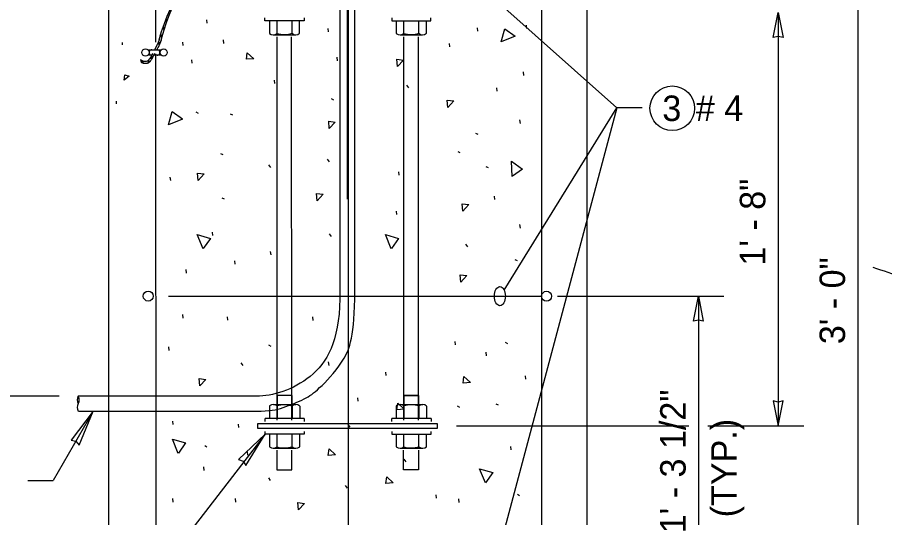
# Model space of a CAD drawing. Extents: x 99862 to 103680, y 99470 to 105076.
# Drawn here: x 101207 to 101751, y 103328 to 103642 of the extents above; entities that cross this region are included whole.
import ezdxf

# ---------------------------------------------------------------- set-up
doc = ezdxf.new("R2010")
doc.units = 0
for name, color, linetype in [('Level 1', 7, 'Continuous'), ('Level 10', 7, 'Continuous'), ('Level 11', 7, 'Continuous'), ('Level 12', 7, 'Continuous'), ('Level 15', 7, 'Continuous'), ('Level 19', 7, 'Continuous'), ('Level 20', 7, 'Continuous'), ('Level 24', 7, 'Continuous'), ('Level 25', 7, 'Continuous'), ('Level 3', 7, 'Continuous'), ('Level 37', 7, 'Continuous'), ('Level 4', 7, 'Continuous'), ('Level 8', 7, 'Continuous')]:
    doc.layers.add(name, color=color, linetype=linetype)

msp = doc.modelspace()

# ---------------------------------------------------------------- linework, layer by layer
at = {"layer": 'Level 1'}
msp.add_line((101564.13, 103688.38), (101564.17, 103232.26), dxfattribs=at)
msp.add_lwpolyline([(101264.13, 103688.38), (101264.17, 103232.26), (101564.17, 103232.26)], dxfattribs=at)
at = {"layer": 'Level 10'}
for centre in [(101289.13, 103466.63), (101538.93, 103466.58)]:
    msp.add_circle(centre, 3.12, dxfattribs=at)
at = {"layer": 'Level 11'}
for p, q in [((101326.18, 103637.91), (101325.95, 103640.09)), ((101402.15, 103632.4), (101401.92, 103634.57)), ((101495.85, 103632.81), (101495.62, 103634.98)), ((101526.51, 103634.59), (101526.28, 103636.76)), ((101311.03, 103623.8), (101310.8, 103625.97)), ((101336.49, 103625.24), (101336.26, 103627.42)), ((101478.27, 103623.08), (101478.03, 103625.25)), ((101316.77, 103612.82), (101316.54, 103615)), ((101407.92, 103614.34), (101407.69, 103616.51)), ((101524.74, 103605.13), (101524.52, 103607.31)), ((101368.6, 103599.99), (101368.37, 103602.17)), ((101451.16, 103598.95), (101452.35, 103597.33)), ((101507.95, 103595.25), (101507.72, 103597.43)), ((101403.77, 103590.57), (101405.21, 103589.86)), ((101318.96, 103582.19), (101320.4, 103581.48)), ((101340.48, 103581.06), (101341.92, 103580.36)), ((101522.48, 103575.03), (101522.25, 103577.2)), ((101494.35, 103568.91), (101495.78, 103568.2)), ((101334.47, 103556.17), (101335.9, 103555.46)), ((101401.35, 103552.6), (101402.54, 103550.99)), ((101483.19, 103557.38), (101484.63, 103556.67)), ((101364.55, 103548.95), (101365.74, 103547.33)), ((101500.86, 103548.01), (101502.29, 103547.3)), ((101446.58, 103542.46), (101446.35, 103544.63)), ((101303.19, 103539.13), (101302.96, 103541.31)), ((101335.31, 103528.37), (101336.75, 103527.66)), ((101506.46, 103527.23), (101506.23, 103529.41)), ((101445.09, 103517.84), (101444.87, 103520.02)), ((101522.49, 103509.37), (101522.26, 103511.55)), ((101329.6, 103504.66), (101329.37, 103506.83)), ((101402.57, 103505.76), (101403.76, 103504.14)), ((101488.19, 103499.21), (101489.38, 103497.59)), ((101366.12, 103492.46), (101365.89, 103494.63)), ((101343.71, 103486.71), (101343.48, 103488.89)), ((101518.97, 103489.7), (101520.41, 103488.99)), ((101313.12, 103481.12), (101312.89, 103483.3)), ((101311.03, 103452.9), (101310.8, 103455.08)), ((101339.06, 103451.46), (101338.83, 103453.64)), ((101392.54, 103451.45), (101392.31, 103453.63)), ((101481.85, 103436.08), (101481.63, 103438.25)), ((101302.19, 103432.55), (101301.95, 103434.73)), ((101364.51, 103436.02), (101365.95, 103435.31)), ((101512.99, 103437.65), (101514.43, 103436.94)), ((101501.22, 103429.28), (101501, 103431.45)), ((101347.25, 103424.8), (101348.44, 103423.18)), ((101402.49, 103423.14), (101402.27, 103425.32)), ((101438.26, 103416.81), (101438.04, 103418.99)), ((101525.87, 103414.49), (101525.64, 103416.67)), ((101420.84, 103400.66), (101420.61, 103402.83)), ((101482.94, 103397.72), (101484.38, 103397.01)), ((101507.19, 103399.09), (101508.63, 103398.39)), ((101304.8, 103386.04), (101304.57, 103388.21)), ((101345.94, 103384.2), (101345.71, 103386.37)), ((101414.33, 103386.09), (101415.52, 103384.47)), ((101324.53, 103372.89), (101325.96, 103372.18)), ((101351.66, 103366.81), (101351.43, 103368.99)), ((101516.8, 103370.16), (101516.57, 103372.34)), ((101449.42, 103364.25), (101450.61, 103362.64)), ((101324.13, 103357.29), (101323.89, 103359.47)), ((101364.49, 103352.65), (101365.68, 103351.03)), ((101412.69, 103347.84), (101413.88, 103346.22)), ((101469.84, 103339.78), (101469.61, 103341.95)), ((101520.6, 103342.29), (101522.03, 103341.58)), ((101304.8, 103337.39), (101304.57, 103339.56)), ((101344.02, 103337.39), (101343.79, 103339.56)), ((101484.21, 103337.24), (101483.98, 103339.41))]:
    msp.add_line(p, q, dxfattribs=at)
for points in [[(101519.28, 103629.76), (101510.38, 103626.15), (101512.72, 103634.35)], [(101512.73, 103634.37), (101519.28, 103629.76)], [(101355.29, 103615.61), (101350.68, 103615.26), (101351.18, 103619.39), (101355.29, 103615.61)], [(101445.45, 103610.69), (101445.09, 103615.29), (101449.23, 103614.79), (101445.45, 103610.69)], [(101476.96, 103585.04), (101476.61, 103589.65), (101480.75, 103589.15), (101476.96, 103585.04)], [(101310.64, 103577.76), (101301.74, 103574.15), (101304.09, 103582.39), (101310.51, 103577.87)], [(101402.66, 103571.73), (101402.31, 103576.33), (101406.44, 103575.83), (101402.66, 103571.73)], [(101517.33, 103541.74), (101516.98, 103551.34), (101523.92, 103546.32), (101517.47, 103541.83)], [(101320.41, 103539.24), (101320.06, 103543.84), (101324.19, 103543.34), (101320.41, 103539.24)], [(101395.09, 103526.44), (101394.74, 103531.04), (101398.87, 103530.54), (101395.09, 103526.44)], [(101486.4, 103520), (101486.05, 103524.6), (101490.18, 103524.11), (101486.4, 103520)], [(101323.47, 103496.34), (101319.86, 103505.24), (101328.1, 103502.89), (101323.58, 103496.46)], [(101441.52, 103496.34), (101437.91, 103505.24), (101446.15, 103502.89), (101441.63, 103496.46)], [(101485.17, 103475.45), (101484.82, 103480.06), (101488.95, 103479.56), (101485.17, 103475.45)], [(101491.22, 103412.47), (101486.61, 103412.12), (101487.11, 103416.25), (101491.22, 103412.47)], [(101321.5, 103410.26), (101321.15, 103414.86), (101325.28, 103414.36), (101321.5, 103410.26)], [(101449.7, 103395.71), (101445.1, 103395.36), (101445.6, 103399.49), (101449.7, 103395.71)], [(101307.95, 103367.94), (101304.34, 103376.84), (101312.58, 103374.49), (101308.06, 103368.07)], [(101406.62, 103366.96), (101402.01, 103366.61), (101402.51, 103370.74), (101406.62, 103366.96)], [(101500.53, 103349.44), (101496.92, 103358.34), (101505.16, 103355.99), (101500.64, 103349.57)], [(101442.82, 103349.4), (101438.22, 103349.05), (101438.72, 103353.19), (101442.82, 103349.4)], [(101383.29, 103332.45), (101382.94, 103337.06), (101387.08, 103336.56), (101383.29, 103332.45)]]:
    msp.add_lwpolyline(points, dxfattribs=at)
at = {"layer": 'Level 12'}
for p, q in [((101365.17, 103639.37), (101365.17, 103631.45)), ((101369.9, 103631.45), (101369.9, 103639.37)), ((101379.35, 103631.54), (101379.35, 103639.41)), ((101384.08, 103631.54), (101384.08, 103639.46)), ((101444.66, 103639.37), (101444.66, 103631.45)), ((101449.39, 103631.45), (101449.39, 103639.37)), ((101458.84, 103631.54), (101458.84, 103639.46)), ((101463.57, 103631.54), (101463.57, 103639.46)), ((101367.69, 103630.65), (101381.72, 103630.65)), ((101447.18, 103630.65), (101461.21, 103630.65)), ((101365.21, 103397.77), (101365.21, 103389.85)), ((101367.73, 103398.57), (101381.75, 103398.57)), ((101369.93, 103397.77), (101369.93, 103389.85)), ((101379.39, 103397.69), (101379.39, 103389.77)), ((101384.12, 103397.69), (101384.12, 103389.77)), ((101444.7, 103397.77), (101444.7, 103389.85)), ((101447.22, 103398.57), (101461.25, 103398.57)), ((101449.43, 103397.77), (101449.43, 103389.85)), ((101458.88, 103397.69), (101458.88, 103389.77)), ((101463.61, 103397.69), (101463.61, 103389.77)), ((101386.97, 103389.81), (101362.36, 103389.81)), ((101362.36, 103388.05), (101362.36, 103389.81)), ((101386.97, 103389.81), (101386.97, 103388.05)), ((101466.46, 103389.81), (101441.85, 103389.81)), ((101441.85, 103388.05), (101441.85, 103389.81)), ((101466.46, 103389.81), (101466.46, 103388.05)), ((101365.21, 103380), (101365.21, 103372.08)), ((101369.93, 103372.08), (101369.93, 103380)), ((101379.39, 103372.16), (101379.39, 103380.04)), ((101384.12, 103372.16), (101384.12, 103380.08)), ((101444.7, 103380), (101444.7, 103372.08)), ((101449.43, 103372.08), (101449.43, 103380)), ((101458.88, 103372.16), (101458.88, 103380.08)), ((101463.61, 103372.16), (101463.61, 103380.08)), ((101367.73, 103371.28), (101381.75, 103371.28)), ((101447.22, 103371.28), (101461.25, 103371.28))]:
    msp.add_line(p, q, dxfattribs=at)
for points in [[(101386.93, 103641.17), (101386.93, 103639.41), (101362.32, 103639.41), (101362.32, 103641.17)], [(101441.81, 103641.17), (101441.81, 103639.41), (101466.42, 103639.41), (101466.42, 103641.17)], [(101386.97, 103381.8), (101386.97, 103380.04), (101362.36, 103380.04), (101362.36, 103381.8)], [(101441.85, 103381.8), (101441.85, 103380.04), (101466.46, 103380.04), (101466.46, 103381.8)]]:
    msp.add_lwpolyline(points, dxfattribs=at)
for centre, radius, start, end in [((101367.53, 103634.55), 3.9, 232.6587, 307.3413), ((101374.48, 103646.27), 15.52, 252.8169, 288.2986), ((101381.72, 103634.26), 3.61, 229.0578, 310.9523), ((101447.02, 103634.55), 3.9, 232.6587, 307.3413), ((101453.97, 103646.27), 15.52, 252.8169, 288.2986), ((101461.21, 103634.26), 3.61, 229.0578, 310.9523), ((101367.57, 103394.68), 3.9, 52.6587, 127.3413), ((101374.52, 103382.95), 15.52, 71.7014, 107.1831), ((101381.75, 103394.96), 3.61, 49.0477, 130.9422), ((101447.06, 103394.68), 3.9, 52.6587, 127.3413), ((101454.01, 103382.95), 15.52, 71.7014, 107.1831), ((101461.25, 103394.96), 3.61, 49.0477, 130.9422), ((101367.57, 103375.17), 3.9, 232.6587, 307.3413), ((101374.52, 103386.9), 15.52, 252.8169, 288.2986), ((101381.75, 103374.89), 3.61, 229.0578, 310.9523), ((101447.06, 103375.17), 3.9, 232.6587, 307.3413), ((101454.01, 103386.9), 15.52, 252.8169, 288.2986), ((101461.25, 103374.89), 3.61, 229.0578, 310.9523)]:
    msp.add_arc(centre, radius, start, end, dxfattribs=at)
at = {"layer": 'Level 15'}
for p, q in [((101734.13, 103694.63), (101734.17, 103232.26)), ((101582.9, 103584.75), (101494.85, 103663.38)), ((101684.13, 103644.56), (101684.17, 103385.18)), ((101582.9, 103584.75), (101497.99, 103265.63)), ((101512.4, 103470.32), (101582.9, 103584.75)), ((101598.9, 103584.75), (101582.9, 103584.75)), ((101545.83, 103466.58), (101650.13, 103466.58)), ((101634.13, 103466.58), (101634.17, 103262.24)), ((101233.25, 103403.85), (101008.17, 103403.85)), ((101254.69, 103394.48), (101229.54, 103350.91)), ((101482.42, 103385.18), (101628.17, 103385.18)), ((101640.17, 103385.18), (101700.17, 103385.18)), ((101362.36, 103380.04), (101210.75, 103183.32)), ((101213.54, 103350.91), (101229.54, 103350.91))]:
    msp.add_line(p, q, dxfattribs=at)
for points in [[(101684.13, 103644.56), (101687.22, 103628.83), (101684.13, 103629.56), (101681.05, 103628.83)], [(101634.13, 103466.58), (101637.22, 103450.86), (101634.13, 103451.59), (101631.05, 103450.86)], [(101684.17, 103385.18), (101687.26, 103400.91), (101684.17, 103400.18), (101681.09, 103400.91)], [(101254.69, 103394.48), (101240.69, 103376.2), (101243.8, 103375.62), (101245.86, 103373.21)], [(101362.37, 103380.03), (101345.64, 103364.22), (101348.62, 103363.15), (101350.26, 103360.45)]]:
    msp.add_lwpolyline(points, close=True, dxfattribs=at)
for centre, start, end in [((101249.28, 103401.52), 150, 210), ((101241.22, 103401.52), 330, 30), ((101249.28, 103396.87), 150, 210.9241)]:
    msp.add_arc(centre, 4.66, start, end, dxfattribs=at)
msp.add_ellipse((101509.66, 103466.63), major_axis=(0, 6), ratio=0.57735, dxfattribs=at)
at = {"layer": 'Level 19'}
for p, q in [((101272.9, 103624.27), (101273.01, 103625.84)), ((101269.19, 103587.39), (101269.3, 103588.97))]:
    msp.add_line(p, q, dxfattribs=at)
msp.add_lwpolyline([(101274.03, 103602.14), (101274.36, 103605.45), (101277.23, 103604.58), (101274.03, 103602.14)], dxfattribs=at)
at = {"layer": 'Level 20'}
msp.add_circle((101617.79, 103584.51), 14, dxfattribs=at)
at = {"layer": 'Level 24'}
msp.add_lwpolyline([(101470.42, 103383.62), (101357.92, 103383.62), (101357.92, 103386.75), (101470.42, 103386.75)], close=True, dxfattribs=at)
at = {"layer": 'Level 25'}
for p, q in [((101293.77, 103754.2), (101293.77, 103625.98)), ((101535.8, 103754.2), (101535.84, 103262.15)), ((101414.02, 103527.42), (101414.02, 103752.42)), ((101414.42, 103650.5), (101414.46, 103262.15)), ((101293.77, 103618.71), (101293.81, 103262.15)), ((101301.84, 103466.63), (101535.8, 103466.63))]:
    msp.add_line(p, q, dxfattribs=at)
at = {"layer": 'Level 3'}
for p, q in [((101409.28, 103754.13), (101409.28, 103464.89)), ((101418.65, 103464.75), (101418.65, 103754.13)), ((101264.08, 103403.85), (101245.25, 103403.85)), ((101357.16, 103403.85), (101264.12, 103403.85)), ((101245.29, 103394.48), (101264.13, 103394.48)), ((101264.15, 103394.48), (101357.14, 103394.48))]:
    msp.add_line(p, q, dxfattribs=at)
for points in [[(101357.14, 103394.48), (101365.25, 103394.46), (101373.29, 103396.11), (101388.18, 103402.42), (101395, 103407.16), (101411.47, 103424.2), (101418.28, 103439.38), (101418.65, 103464.75)], [(101409.28, 103464.89), (101408.82, 103437.99), (101393.54, 103411.59), (101366.76, 103403.83), (101357.16, 103403.85)]]:
    msp.add_open_spline(points, degree=3, dxfattribs=at)
at = {"layer": 'Level 37'}
msp.add_ellipse((102885.43, 104054.93), major_axis=(1749.63, 26.45), ratio=0.419197, start_param=3.995063, end_param=4.008995, dxfattribs=at)
at = {"layer": 'Level 4'}
for p, q in [((101369.67, 103629.4), (101369.71, 103388.74)), ((101379.08, 103388.74), (101379.05, 103629.4)), ((101449.22, 103629.4), (101449.26, 103388.74)), ((101458.63, 103388.74), (101458.6, 103629.4)), ((101446.85, 103466.63), (101446.95, 103466.63)), ((101371.29, 103404.26), (101369.92, 103404.26)), ((101371.29, 103404.26), (101369.92, 103404.26)), ((101369.92, 103404.26), (101369.92, 103398.57)), ((101379.29, 103404.26), (101371.29, 103404.26)), ((101379.29, 103404.26), (101371.29, 103404.26)), ((101379.29, 103398.57), (101379.29, 103404.26)), ((101458.84, 103404.26), (101449.47, 103404.26)), ((101449.47, 103404.26), (101457.47, 103404.26)), ((101449.47, 103404.26), (101449.47, 103398.57)), ((101457.47, 103404.26), (101458.84, 103404.26)), ((101458.84, 103398.57), (101458.84, 103404.26))]:
    msp.add_line(p, q, dxfattribs=at)
for points in [[(101369.71, 103370.02), (101369.71, 103357.72), (101379.08, 103357.72), (101379.08, 103370.02)], [(101458.63, 103370.02), (101458.63, 103357.72), (101449.26, 103357.72), (101449.26, 103370.02)]]:
    msp.add_lwpolyline(points, dxfattribs=at)
at = {"layer": 'Level 8'}
for p, q in [((101301.14, 103639.93), (101300.24, 103639.93)), ((101298, 103634.28), (101298.9, 103634.28)), ((101299.22, 103635.12), (101298.32, 103635.12)), ((101299.89, 103639.1), (101300.8, 103639.1)), ((101296.28, 103629.46), (101297.16, 103629.46)), ((101297.45, 103630.3), (101296.57, 103630.3)), ((101295.06, 103624.89), (101295.94, 103624.89)), ((101296.23, 103625.73), (101295.35, 103625.73)), ((101288.86, 103621.24), (101297.32, 103621.24)), ((101291.27, 103617.8), (101288.86, 103617.81)), ((101297.32, 103617.8), (101291.27, 103617.8)), ((101284.27, 103614.86), (101284.7, 103613.29)), ((101285.93, 103614.05), (101285.07, 103614.37)), ((101285.07, 103614.37), (101285.13, 103613.28)), ((101285.13, 103613.28), (101285.99, 103612.95)), ((101285.99, 103612.95), (101285.93, 103614.05)), ((101289.06, 103614.36), (101288.99, 103614.32)), ((101288.99, 103614.32), (101289.13, 103613.41)), ((101289.92, 103613.93), (101289.06, 103614.36)), ((101289.13, 103613.41), (101289.92, 103613.93)), ((101290.71, 103616.82), (101290.33, 103615.99)), ((101290.33, 103615.99), (101291.43, 103615.99)), ((101291.8, 103616.82), (101290.71, 103616.82)), ((101291.43, 103615.99), (101291.8, 103616.82))]:
    msp.add_line(p, q, dxfattribs=at)
for centre in [(101287.38, 103619.53), (101298.8, 103619.52)]:
    msp.add_circle(centre, 2.26, dxfattribs=at)
for centre, start, end in [((101291.37, 103619.52), 89.5362, 271.7935), ((101294.73, 103619.52), 267.0924, 91.4915)]:
    msp.add_arc(centre, 1.72, start, end, dxfattribs=at)
for points, degree in [([(101295.94, 103627.5), (101312.4, 103683.94), (101386.21, 103718.5), (101400.62, 103786.62), (101389.07, 103859.78), (101409.48, 103891.5)], 3), ([(101297.21, 103627.19), (101303.17, 103648), (101312.24, 103663.56), (101332.2, 103688.12), (101343.09, 103697.11), (101358.06, 103709.05), (101362.81, 103712.77), (101369.25, 103718.4), (101371.28, 103720.29), (101375.05, 103724.13), (101376.8, 103726.08), (101384.89, 103735.98), (101389.27, 103744.4), (101394.96, 103762.55), (101396.27, 103772.27), (101396.73, 103785.49), (101396.77, 103788.19), (101396.74, 103793.7), (101396.67, 103796.51), (101396.38, 103805.1), (101396.07, 103811.03), (101395.43, 103829.17), (101395.37, 103841.77), (101399.23, 103866.71), (101403.14, 103879.06), (101410.66, 103890.74)], 3), ([(101300.24, 103639.93), (101300.12, 103639.66), (101300.01, 103639.38), (101299.89, 103639.1)], 2), ([(101300.8, 103639.1), (101300.91, 103639.38), (101301.03, 103639.66), (101301.14, 103639.93)], 2), ([(101298.32, 103635.12), (101298.21, 103634.84), (101298.11, 103634.56), (101298, 103634.28)], 2), ([(101298.9, 103634.28), (101299, 103634.56), (101299.11, 103634.84), (101299.22, 103635.12)], 2), ([(101296.57, 103630.3), (101296.47, 103630.02), (101296.37, 103629.74), (101296.28, 103629.46)], 2), ([(101297.16, 103629.46), (101297.26, 103629.74), (101297.35, 103630.02), (101297.45, 103630.3)], 2), ([(101295.94, 103627.5), (101295.08, 103625.06), (101294.06, 103622.9), (101293.11, 103621.24)], 3), ([(101297.21, 103627.19), (101296.57, 103625.66), (101296.14, 103624.55), (101295.74, 103623.64), (101295.69, 103623.54), (101295.61, 103623.36), (101295.57, 103623.27), (101295.43, 103623), (101295.33, 103622.8), (101295.01, 103622.18), (101294.77, 103621.73), (101294.49, 103621.24)], 3), ([(101295.35, 103625.73), (101295.25, 103625.45), (101295.15, 103625.17), (101295.06, 103624.89)], 2), ([(101295.94, 103624.89), (101296.04, 103625.17), (101296.14, 103625.45), (101296.23, 103625.73)], 2), ([(101291.79, 103618.88), (101291.31, 103617.98), (101289.9, 103615.14), (101288.5, 103613.86), (101287.02, 103613.79), (101286.4, 103613.79), (101284.27, 103614.86)], 3), ([(101293.17, 103618.89), (101293, 103618.58), (101292.68, 103618), (101292.31, 103617.27), (101292.1, 103616.86), (101291.99, 103616.65), (101291.96, 103616.58), (101291.89, 103616.43), (101291.85, 103616.36), (101291.53, 103615.72), (101291.25, 103615.23), (101290.7, 103614.39), (101290.44, 103614.03), (101290.1, 103613.7), (101290.07, 103613.66), (101289.99, 103613.59), (101289.96, 103613.56), (101289.85, 103613.47), (101289.78, 103613.41), (101289.57, 103613.25), (101289.42, 103613.15), (101288.96, 103612.88), (101288.63, 103612.75), (101288.19, 103612.66), (101288.1, 103612.65), (101287.97, 103612.63), (101287.92, 103612.63), (101287.86, 103612.62), (101287.83, 103612.62), (101287.8, 103612.62), (101287.68, 103612.61), (101287.57, 103612.61), (101287.28, 103612.59), (101287.12, 103612.59), (101286.91, 103612.58), (101286.84, 103612.58), (101286.77, 103612.58), (101286.75, 103612.58), (101286.72, 103612.58), (101286.72, 103612.58), (101286.71, 103612.58), (101286.71, 103612.58), (101286.68, 103612.58), (101286.66, 103612.58), (101286.49, 103612.59), (101286.4, 103612.61), (101286.14, 103612.68), (101286, 103612.73), (101285.67, 103612.86), (101285.49, 103612.94), (101285.1, 103613.12), (101284.88, 103613.22), (101284.65, 103613.33)], 3)]:
    msp.add_open_spline(points, degree=degree, dxfattribs=at)

# ---------------------------------------------------------------- texts
at = {"layer": 'Level 20'}
for s, p in [('3', (101611.53, 103576.51)), ('    # 4', (101608.75, 103576.6))]:
    msp.add_text(s, height=16, dxfattribs=at).set_placement(p)
for s, p in [('1\' - 8"', (101676.13, 103485.82)), ('3\' - 0"', (101726.13, 103436.49)), ('1\' - 3 1/2"', (101626.17, 103317.84)), ('(TYP.)', (101658.17, 103327.84))]:
    msp.add_text(s, height=16, rotation=90, dxfattribs=at).set_placement(p)

doc.saveas('drawing.dxf')
